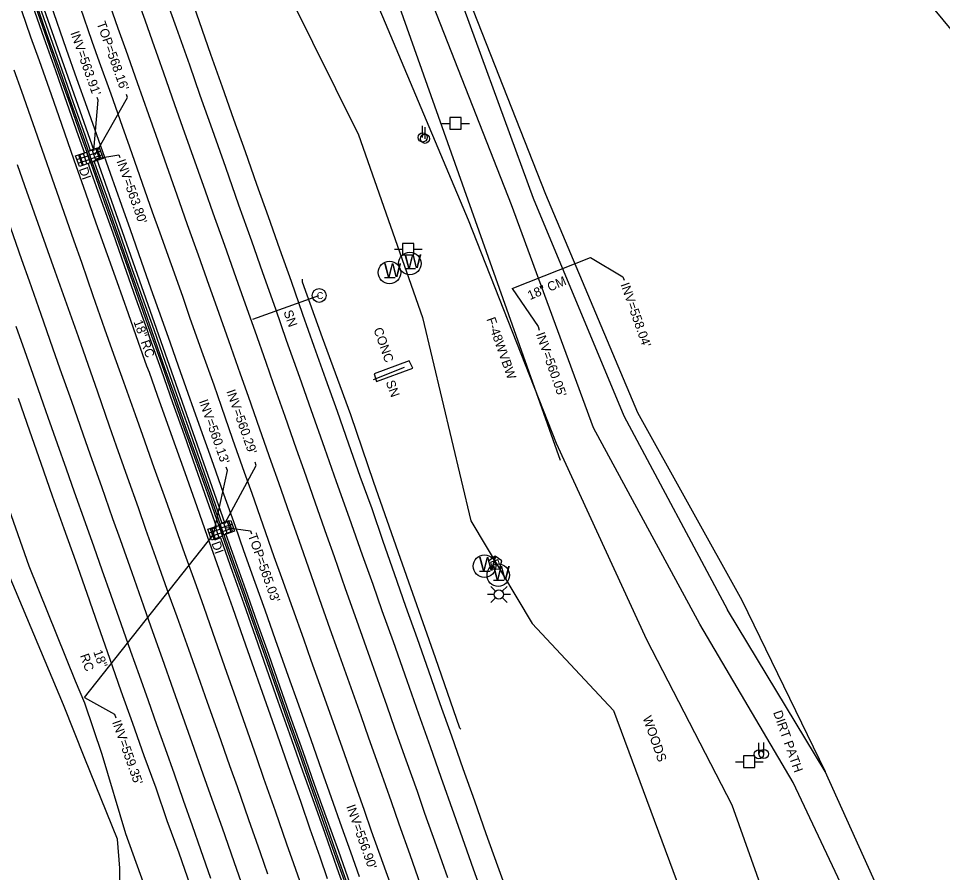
# Model space of a CAD drawing. Extents: x 2004847 to 2009016, y 1134161 to 1140101.
# Drawn here: x 2006254.5 to 2006657.2, y 1135789.7 to 1136161.7 of the extents above; entities that cross this region are included whole.
import ezdxf

# ---------------------------------------------------------------- set-up
doc = ezdxf.new("R2010")
doc.units = 0
for name, color, linetype in [('RD_EX_BldgApp', 7, 'Continuous'), ('RD_EX_Conc', 7, 'Continuous'), ('RD_EX_DR_Inlet', 7, 'Continuous'), ('RD_EX_DR_Inlet_txCode', 7, 'Continuous'), ('RD_EX_DR_Pipe', 7, 'Continuous'), ('RD_EX_DR_Pipe_txCode', 7, 'Continuous'), ('RD_EX_Driveway', 7, 'Continuous'), ('RD_EX_Fence_Other', 7, 'Continuous'), ('RD_EX_GuardRail', 7, 'Continuous'), ('RD_EX_H2O', 7, 'Continuous'), ('RD_EX_Pavement_Markings', 7, 'Continuous'), ('RD_EX_Road', 7, 'Continuous'), ('RD_EX_SU_Elec', 7, 'Continuous'), ('RD_EX_UT', 7, 'Continuous'), ('RD_EX_VEG', 7, 'Continuous'), ('RD_Sketch3', 7, 'Continuous')]:
    doc.layers.add(name, color=color, linetype=linetype)

msp = doc.modelspace()

# ---------------------------------------------------------------- linework, layer by layer
at = {"layer": 'RD_EX_BldgApp'}
for p, q in [((2006356.56, 1136030.74), (2006385.39, 1136041)), ((2006409.26, 1136004.5), (2006422.73, 1136009.77))]:
    msp.add_line(p, q, dxfattribs=at)
msp.add_circle((2006385.55, 1136041.06), 3, dxfattribs=at)
at = {"layer": 'RD_EX_Conc'}
for points in [[(2006261.87, 1136166.89), (2006266.82, 1136152.8), (2006271.82, 1136138.65), (2006276.81, 1136124.49), (2006281.81, 1136110.34), (2006286.83, 1136096.21), (2006291.85, 1136082.05), (2006296.79, 1136068), (2006301.8, 1136053.79), (2006306.81, 1136039.66), (2006311.8, 1136025.52), (2006316.78, 1136011.4), (2006321.74, 1135997.2), (2006326.74, 1135983.07), (2006331.82, 1135968.96), (2006336.81, 1135954.83), (2006341.84, 1135940.67), (2006346.82, 1135926.54), (2006351.83, 1135912.38), (2006356.79, 1135898.27), (2006361.81, 1135884.09), (2006366.78, 1135869.96), (2006371.77, 1135855.83), (2006376.79, 1135841.7), (2006381.8, 1135827.55), (2006386.76, 1135813.4), (2006392.11, 1135798.33), (2006397.11, 1135784.17)], [(2006262.53, 1136167.13), (2006267.48, 1136153.03), (2006272.5, 1136138.89), (2006277.48, 1136124.73), (2006282.5, 1136110.58), (2006287.49, 1136096.45), (2006292.51, 1136082.29), (2006297.49, 1136068.23), (2006302.5, 1136054.04), (2006307.51, 1136039.91), (2006312.48, 1136025.76), (2006317.45, 1136011.63), (2006322.43, 1135997.44), (2006327.43, 1135983.31), (2006332.53, 1135969.21), (2006337.53, 1135955.08), (2006342.52, 1135940.91), (2006347.52, 1135926.79), (2006352.54, 1135912.63), (2006357.48, 1135898.51), (2006362.52, 1135884.35), (2006367.5, 1135870.22), (2006372.49, 1135856.09), (2006377.5, 1135841.95), (2006382.51, 1135827.8), (2006387.53, 1135813.67), (2006392.86, 1135798.6), (2006397.85, 1135784.43)]]:
    msp.add_lwpolyline(points, dxfattribs=at)
msp.add_lwpolyline([(2006426.35, 1136009.4), (2006424.76, 1136012.54), (2006409.51, 1136006.93), (2006410.51, 1136003.52)], close=True, dxfattribs=at)
at = {"layer": 'RD_EX_DR_Inlet'}
for p, q in [((2006282.63, 1136102.99), (2006284.25, 1136098.26)), ((2006285.54, 1136102.24), (2006290.27, 1136103.86)), ((2006286.6, 1136104.4), (2006288.22, 1136099.67)), ((2006288.21, 1136104.95), (2006289.83, 1136100.22)), ((2006279.96, 1136100.28), (2006284.69, 1136101.9)), ((2006280.51, 1136098.67), (2006285.24, 1136100.29)), ((2006281.02, 1136102.44), (2006282.64, 1136097.71)), ((2006286.1, 1136100.63), (2006290.82, 1136102.25)), ((2006343.89, 1135942), (2006345.51, 1135937.27)), ((2006345.5, 1135942.55), (2006347.12, 1135937.82)), ((2006337.59, 1135937.64), (2006342.32, 1135939.27)), ((2006338.14, 1135936.04), (2006342.87, 1135937.66)), ((2006338.64, 1135939.8), (2006340.26, 1135935.07)), ((2006340.25, 1135940.36), (2006341.87, 1135935.63)), ((2006342.84, 1135939.84), (2006347.57, 1135941.46)), ((2006343.39, 1135938.23), (2006348.12, 1135939.86))]:
    msp.add_line(p, q, dxfattribs=at)
for points in [[(2006281.03, 1136097.16), (2006279.41, 1136101.89), (2006284.14, 1136103.51), (2006285.76, 1136098.78)], [(2006286.61, 1136099.11), (2006284.99, 1136103.84), (2006289.72, 1136105.47), (2006291.34, 1136100.74)], [(2006343.91, 1135936.72), (2006342.28, 1135941.45), (2006347.01, 1135943.07), (2006348.64, 1135938.34)], [(2006338.66, 1135934.52), (2006337.03, 1135939.25), (2006341.76, 1135940.87), (2006343.39, 1135936.15)]]:
    msp.add_lwpolyline(points, close=True, dxfattribs=at)
at = {"layer": 'RD_EX_DR_Inlet_txCode'}
for points in [[(2006287.37, 1136104.14), (2006289.17, 1136126.09), (2006288.74, 1136127.29)], [(2006287.96, 1136102.44), (2006302.01, 1136127.21), (2006301.52, 1136128.59)], [(2006288.55, 1136100.7), (2006298.24, 1136102.27), (2006298.64, 1136101.13)], [(2006503.74, 1136057.52), (2006517.92, 1136049.14), (2006518.42, 1136047.71)], [(2006469.59, 1136044.05), (2006480.94, 1136027.47), (2006481.47, 1136025.99)], [(2006339.54, 1135937), (2006345.59, 1135964.84), (2006345.08, 1135966.28)], [(2006344.44, 1135941.71), (2006358.12, 1135967.04), (2006357.63, 1135968.43)], [(2006345.05, 1135940.04), (2006355.59, 1135938.56), (2006356.04, 1135937.27)], [(2006283.21, 1135866.02), (2006296.3, 1135858.7), (2006296.89, 1135857.04)]]:
    msp.add_lwpolyline(points, dxfattribs=at)
at = {"layer": 'RD_EX_DR_Pipe'}
for p, q in [((2006230.99, 1136263.47), (2006287.37, 1136104.14)), ((2006288.55, 1136100.7), (2006344.44, 1135941.71)), ((2006469.59, 1136044.05), (2006503.74, 1136057.52)), ((2006283.21, 1135866.02), (2006339.54, 1135937))]:
    msp.add_line(p, q, dxfattribs=at)
at = {"layer": 'RD_EX_Driveway'}
for points in [[(2006320.55, 1136558.36), (2006344.22, 1136462.95), (2006367.47, 1136387.76), (2006397.5, 1136288.99), (2006440.84, 1136187.25), (2006478.74, 1136083.47), (2006518.32, 1135988.65), (2006563.43, 1135904.15)], [(2006551.41, 1135897.85), (2006505.13, 1135983.38), (2006469.38, 1136080.46), (2006429.34, 1136182.74), (2006387.99, 1136286.09), (2006354.86, 1136380.53), (2006334.03, 1136460.8), (2006306.37, 1136551.19)], [(2006666.77, 1135696.37), (2006647.18, 1135742.63), (2006606.03, 1135833.76), (2006563.43, 1135904.15)], [(2006656.28, 1135692.15), (2006634.83, 1135738.49), (2006592.17, 1135828.94), (2006551.41, 1135897.85)]]:
    msp.add_lwpolyline(points, dxfattribs=at)
at = {"layer": 'RD_EX_Fence_Other'}
msp.add_lwpolyline([(2006288.09, 1136544.58), (2006318.68, 1136456.24), (2006344.96, 1136379.7), (2006379.57, 1136282.04), (2006416.49, 1136178.27), (2006490.52, 1135969.29)], dxfattribs=at)
at = {"layer": 'RD_EX_GuardRail'}
msp.add_lwpolyline([(2006447.28, 1135852.21), (2006446.78, 1135852.58), (2006436.25, 1135883.27), (2006420.92, 1135926.56), (2006409.33, 1135959.56), (2006399.37, 1135989.06), (2006386.98, 1136022.61), (2006378.24, 1136046.92), (2006378.3, 1136048.22)], dxfattribs=at)
at = {"layer": 'RD_EX_H2O'}
for points in [[(2006438.3, 1136552.85), (2006448.54, 1136539.41), (2006461.27, 1136510.56), (2006479.77, 1136475.59), (2006499.97, 1136438.29), (2006517.79, 1136392.8), (2006547.32, 1136356.98), (2006571.18, 1136336.4), (2006576.82, 1136324.85), (2006567.33, 1136313.35), (2006581.05, 1136268.26), (2006602.92, 1136221.41), (2006633.34, 1136190.16), (2006666.45, 1136150.11), (2006686.25, 1136119.02), (2006695.17, 1136104.33)], [(2006169.58, 1136177.63), (2006207.33, 1136068.49), (2006240.4, 1135975.91), (2006259.05, 1135923.24), (2006279.18, 1135873.19), (2006283.21, 1135863.56), (2006290.81, 1135841.34), (2006301.16, 1135806.7), (2006317.11, 1135762.46), (2006327.77, 1135727.04)]]:
    msp.add_lwpolyline(points, dxfattribs=at)
at = {"layer": 'RD_EX_Pavement_Markings'}
for points in [[(2006304.5, 1136175.2), (2006309.51, 1136161.14), (2006312.8, 1136151.89), (2006317.67, 1136138.08), (2006322.55, 1136124.28), (2006326.05, 1136114.38), (2006335.84, 1136086.59), (2006339.22, 1136077.1), (2006344.24, 1136063.01), (2006349.26, 1136048.91), (2006352.62, 1136039.44), (2006357.45, 1136025.71), (2006362.28, 1136011.98), (2006365.56, 1136002.66), (2006370.55, 1135988.48), (2006375.54, 1135974.3), (2006378.82, 1135964.97), (2006383.8, 1135950.79), (2006388.78, 1135936.62), (2006392.07, 1135927.31), (2006396.94, 1135913.45), (2006401.81, 1135899.6), (2006405.11, 1135890.18), (2006410.07, 1135876.23), (2006415.04, 1135862.28), (2006418.42, 1135852.59), (2006423.3, 1135838.85), (2006428.18, 1135825.11), (2006431.52, 1135815.53), (2006436.48, 1135801.53), (2006441.44, 1135787.53)], [(2006292.95, 1136171.41), (2006297.85, 1136157.46), (2006301.32, 1136147.84), (2006306.23, 1136133.88), (2006311.14, 1136119.91), (2006314.29, 1136110.91), (2006324.51, 1136081.92), (2006328.06, 1136072.02), (2006332.77, 1136058.78), (2006337.48, 1136045.54), (2006340.96, 1136035.87), (2006346.03, 1136021.41), (2006351.11, 1136006.96), (2006354.61, 1135997.15), (2006359.52, 1135983), (2006364.43, 1135968.85), (2006367.79, 1135959.55), (2006372.66, 1135945.79), (2006377.53, 1135932.02), (2006380.87, 1135922.38), (2006385.57, 1135909.14), (2006390.26, 1135895.9), (2006393.56, 1135886.58), (2006398.61, 1135872.34), (2006403.66, 1135858.1), (2006407.04, 1135848.4), (2006411.96, 1135834.54), (2006416.89, 1135820.68), (2006420.32, 1135810.99), (2006425.05, 1135797.61), (2006429.77, 1135784.24)], [(2006457.26, 1135778.74), (2006452.86, 1135791.22), (2006449.06, 1135801.89), (2006444.41, 1135815.19), (2006438.76, 1135831.14), (2006434.02, 1135844.53), (2006429.04, 1135858.64), (2006423.83, 1135873.28), (2006417.88, 1135890.17), (2006413.07, 1135903.74), (2006409.03, 1135915.18), (2006404.42, 1135927.97), (2006398.77, 1135944.02), (2006393.15, 1135959.91), (2006388.07, 1135974.41), (2006382.09, 1135991.31), (2006377.14, 1136005.38), (2006371.36, 1136021.46), (2006366.61, 1136035.13), (2006361.03, 1136050.85), (2006356.19, 1136064.71), (2006350.6, 1136080.36), (2006344.85, 1136096.72), (2006339.03, 1136113.21), (2006333.72, 1136128.12), (2006329.11, 1136141.41), (2006323.36, 1136157.6), (2006317.84, 1136173.05)], [(2006268.38, 1136168.14), (2006275.31, 1136148.35), (2006279.82, 1136135.56), (2006284.23, 1136123.1), (2006289.34, 1136108.73), (2006294.45, 1136094.3), (2006299.46, 1136080.4), (2006303.13, 1136069.76), (2006308.01, 1136056.03), (2006312.24, 1136044.01), (2006316.82, 1136031.06), (2006320.59, 1136020.42), (2006324.08, 1136010.42), (2006327.45, 1136000.9), (2006331.69, 1135989.05), (2006335.86, 1135977.31), (2006339.29, 1135967.61), (2006343.83, 1135954.72), (2006348.87, 1135940.55), (2006352.61, 1135929.92), (2006357.45, 1135916.25), (2006361.79, 1135904.14), (2006366.37, 1135891.15), (2006372.79, 1135873.24), (2006375.78, 1135864.83), (2006381.87, 1135847.6), (2006386.58, 1135834.27), (2006390.82, 1135822.34), (2006395.34, 1135809.63), (2006399.18, 1135798.7), (2006402.97, 1135787.95)], [(2006255.84, 1136165.21), (2006259.8, 1136153.76), (2006263.5, 1136143.4), (2006268.72, 1136128.59), (2006273.19, 1136115.63), (2006278.64, 1136100.15), (2006283.65, 1136085.81), (2006288.26, 1136072.75), (2006293.21, 1136058.96), (2006297.31, 1136047.21), (2006302.25, 1136033.21), (2006306.69, 1136020.72), (2006310.36, 1136010.39), (2006311.39, 1136007.64), (2006314.99, 1135997.61), (2006320.94, 1135980.88), (2006326.93, 1135963.95), (2006332.21, 1135949.11), (2006336.72, 1135936.29), (2006342.74, 1135919.39), (2006347.78, 1135905.16), (2006352.46, 1135891.8), (2006356.26, 1135881.09), (2006360.7, 1135868.34), (2006365.07, 1135855.99), (2006369.41, 1135843.43), (2006372.94, 1135833.44), (2006377.49, 1135820.34), (2006381.49, 1135808.8), (2006385.83, 1135796.55), (2006389.06, 1135787.19)], [(2006281.31, 1136166.68), (2006286.53, 1136151.84), (2006289.7, 1136142.85), (2006294.7, 1136128.81), (2006299.7, 1136114.78), (2006302.84, 1136105.78), (2006312.77, 1136077.53), (2006316.03, 1136068.31), (2006321.01, 1136054.51), (2006325.98, 1136040.71), (2006329.08, 1136031.65), (2006334.33, 1136016.89), (2006339.59, 1136002.12), (2006342.82, 1135992.86), (2006347.84, 1135978.51), (2006352.87, 1135964.16), (2006356.14, 1135954.99), (2006360.98, 1135941.2), (2006365.83, 1135927.41), (2006369.1, 1135918.2), (2006373.89, 1135904.84), (2006378.69, 1135891.49), (2006381.86, 1135882.28), (2006387.11, 1135867.68), (2006392.37, 1135853.07), (2006395.53, 1135843.99), (2006400.34, 1135830.44), (2006405.14, 1135816.89), (2006408.22, 1135807.91), (2006413.27, 1135793.79), (2006418.33, 1135779.67)], [(2006252.54, 1136139.29), (2006255.81, 1136130.1), (2006265.75, 1136101.8), (2006269.06, 1136092.34), (2006278.6, 1136064.82), (2006278.6, 1136064.81), (2006281.89, 1136055.63), (2006286.95, 1136041.1), (2006292.01, 1136026.57), (2006295.15, 1136017.56), (2006300.24, 1136003.4), (2006305.32, 1135989.23), (2006308.52, 1135980.21), (2006313.55, 1135966.18), (2006318.58, 1135952.15), (2006321.9, 1135942.73), (2006326.92, 1135928.7), (2006331.94, 1135914.68), (2006335.34, 1135905.26), (2006340.26, 1135891.13), (2006345.19, 1135877), (2006348.37, 1135868.02), (2006353.28, 1135853.92), (2006358.19, 1135839.83), (2006361.28, 1135830.86), (2006366.3, 1135816.55), (2006371.33, 1135802.23), (2006374.42, 1135793.72), (2006379.49, 1135779.21)], [(2006253.89, 1136098.1), (2006257.1, 1136088.96), (2006267.09, 1136060.62), (2006270.32, 1136051.66), (2006275.39, 1136037.45), (2006280.46, 1136023.24), (2006283.69, 1136013.97), (2006288.88, 1135999.13), (2006294.06, 1135984.29), (2006297.13, 1135975.61), (2006301.88, 1135962.13), (2006306.63, 1135948.65), (2006309.9, 1135939.33), (2006314.99, 1135924.99), (2006320.08, 1135910.66), (2006323.44, 1135901.25), (2006328.53, 1135886.96), (2006333.62, 1135872.68), (2006336.74, 1135863.86), (2006341.62, 1135850.09), (2006346.51, 1135836.32), (2006349.81, 1135827.12), (2006354.8, 1135812.79), (2006359.78, 1135798.45), (2006362.98, 1135789.13)], [(2006245.9, 1136084.76), (2006255.88, 1136056.69), (2006259.17, 1136047.5), (2006264.26, 1136032.86), (2006269.34, 1136018.21), (2006272.57, 1136009.16), (2006277.54, 1135995.01), (2006282.52, 1135980.86), (2006285.78, 1135971.71), (2006290.66, 1135957.82), (2006295.54, 1135943.93), (2006298.87, 1135934.74), (2006303.95, 1135920.34), (2006309.02, 1135905.93), (2006312.25, 1135896.67), (2006317.08, 1135882.97), (2006321.91, 1135869.26), (2006325.28, 1135859.9), (2006330.07, 1135846.32), (2006334.87, 1135832.73), (2006338, 1135823.74), (2006343.21, 1135809.16), (2006348.42, 1135794.59), (2006351.62, 1135785.4)], [(2006253.34, 1136027.64), (2006257.17, 1136017.04), (2006260.77, 1136006.77), (2006265.25, 1135993.82), (2006267.32, 1135988.03), (2006271.36, 1135976.53), (2006275.22, 1135965.57), (2006278.76, 1135955.55), (2006283.54, 1135942.16), (2006287.31, 1135931.57), (2006290.85, 1135921.55), (2006294.71, 1135910.59), (2006299.09, 1135898.2), (2006303.3, 1135886.2), (2006307.05, 1135875.74), (2006310.97, 1135864.72), (2006314.7, 1135854.22), (2006318.39, 1135843.68), (2006322.29, 1135832.73), (2006326.33, 1135821.27), (2006330.17, 1135810.25), (2006333.84, 1135799.77), (2006338.19, 1135787.27)]]:
    msp.add_lwpolyline(points, dxfattribs=at)
at = {"layer": 'RD_EX_Road'}
msp.add_line((2006280.83, 1136102.22), (2006283.22, 1136103.07), dxfattribs=at)
for points in [[(2006227.36, 1136261.64), (2006230.66, 1136252.21), (2006235.69, 1136238.07), (2006240.66, 1136223.94), (2006245.65, 1136209.78), (2006250.61, 1136195.62), (2006255.61, 1136181.46), (2006260.63, 1136167.31), (2006265.59, 1136153.2), (2006270.58, 1136139.03), (2006275.54, 1136124.85), (2006280.51, 1136110.73), (2006283.22, 1136103.07)], [(2006229.89, 1136262.56), (2006233.47, 1136252.43), (2006238.49, 1136238.31), (2006243.5, 1136224.15), (2006248.45, 1136210.01), (2006253.42, 1136195.84), (2006258.41, 1136181.74), (2006263.44, 1136167.55), (2006268.39, 1136153.44), (2006273.39, 1136139.29), (2006278.37, 1136125.14), (2006283.39, 1136111), (2006285.76, 1136104.24)], [(2006327.95, 1136175.43), (2006333.21, 1136160.31), (2006338.13, 1136146.14), (2006343.2, 1136131.94), (2006348.23, 1136117.9), (2006353.26, 1136103.74), (2006358.29, 1136089.6), (2006363.28, 1136075.51), (2006368.31, 1136061.31), (2006373.29, 1136047.22), (2006378.25, 1136032.98), (2006383.2, 1136018.95), (2006388.36, 1136004.79), (2006393.38, 1135990.68), (2006398.3, 1135976.47), (2006403.28, 1135962.36), (2006408.43, 1135948.27), (2006413.28, 1135934.07), (2006418.19, 1135919.98), (2006423.17, 1135905.78), (2006428.21, 1135891.63), (2006433.24, 1135877.5), (2006438.17, 1135863.38), (2006443.16, 1135849.2), (2006448.13, 1135835.07), (2006453.17, 1135820.95), (2006458.23, 1135806.78), (2006463.24, 1135792.68), (2006468.28, 1135778.65)], [(2006287.36, 1136099.73), (2006290.39, 1136100.72), (2006288.76, 1136105.26), (2006285.76, 1136104.24)], [(2006284.83, 1136098.54), (2006282.42, 1136097.71), (2006280.83, 1136102.22)], [(2006287.36, 1136099.73), (2006288.38, 1136096.86), (2006293.43, 1136082.71), (2006298.38, 1136068.62), (2006303.37, 1136054.44), (2006308.38, 1136040.31), (2006313.44, 1136026.18), (2006318.38, 1136012.04), (2006323.41, 1135997.88), (2006328.4, 1135983.75), (2006333.37, 1135969.6), (2006338.37, 1135955.47), (2006343.15, 1135941.91)], [(2006284.83, 1136098.54), (2006285.51, 1136096.58), (2006290.56, 1136082.47), (2006295.55, 1136068.36), (2006300.56, 1136054.17), (2006305.52, 1136040.04), (2006310.53, 1136025.92), (2006311.66, 1136022.75), (2006316.62, 1136008.62), (2006321.56, 1135994.44), (2006326.65, 1135980.32), (2006331.62, 1135966.17), (2006336.56, 1135952.03), (2006340.87, 1135940.09)], [(2006254.34, 1135996.31), (2006259.32, 1135982.11), (2006264.29, 1135967.95), (2006269.23, 1135953.79), (2006274.29, 1135939.63), (2006279.29, 1135925.53), (2006284.28, 1135911.39), (2006289.19, 1135897.21), (2006294.13, 1135883.08), (2006299.17, 1135868.91), (2006304.18, 1135854.78), (2006309.14, 1135840.67), (2006314.43, 1135826.61), (2006319.18, 1135812.42), (2006324.36, 1135798.33), (2006329.27, 1135784.11)], [(2006344.78, 1135937.35), (2006347.8, 1135938.33), (2006346.2, 1135942.86), (2006343.15, 1135941.91)], [(2006342.5, 1135935.43), (2006339.93, 1135934.45), (2006338.21, 1135939.21), (2006340.87, 1135940.09)], [(2006342.5, 1135935.43), (2006342.62, 1135935.08), (2006347.62, 1135920.94), (2006352.64, 1135906.78), (2006357.59, 1135892.65), (2006362.64, 1135878.5), (2006367.6, 1135864.37), (2006372.63, 1135850.2), (2006377.56, 1135836.08), (2006382.68, 1135821.94), (2006387.99, 1135806.9), (2006393.28, 1135791.77), (2006398.31, 1135777.7), (2006403.3, 1135763.51), (2006403.59, 1135762.69)], [(2006344.78, 1135937.35), (2006348.35, 1135927.18), (2006353.37, 1135913.03), (2006358.38, 1135898.92), (2006363.42, 1135884.76), (2006368.4, 1135870.63), (2006373.39, 1135856.5), (2006378.43, 1135842.38), (2006383.43, 1135828.23), (2006388.51, 1135814.12), (2006393.91, 1135799.08), (2006398.91, 1135784.92), (2006403.76, 1135770.76), (2006405.94, 1135764.55)]]:
    msp.add_lwpolyline(points, dxfattribs=at)
at = {"layer": 'RD_EX_SU_Elec'}
msp.add_lwpolyline([(2006465.2, 1135925.43), (2006462.24, 1135927.46), (2006459.4, 1135925.28), (2006460.59, 1135921.9), (2006464.17, 1135921.99)], close=True, dxfattribs=at)
at = {"layer": 'RD_EX_UT'}
for p, q in [((2006430.63, 1136109.89), (2006430.63, 1136114.89)), ((2006439, 1136115.98), (2006442.47, 1136115.98)), ((2006447.44, 1136118.55), (2006442.44, 1136118.55)), ((2006442.44, 1136118.55), (2006442.44, 1136113.55)), ((2006447.36, 1136115.98), (2006451, 1136115.98)), ((2006447.44, 1136113.55), (2006447.44, 1136118.55)), ((2006431.69, 1136109.31), (2006431.69, 1136114.31)), ((2006442.44, 1136113.55), (2006447.44, 1136113.55)), ((2006426.79, 1136063.73), (2006421.79, 1136063.73)), ((2006421.79, 1136063.73), (2006421.79, 1136058.73)), ((2006426.79, 1136058.73), (2006426.79, 1136063.73)), ((2006418.36, 1136061.16), (2006421.83, 1136061.16)), ((2006421.79, 1136058.73), (2006426.79, 1136058.73)), ((2006426.72, 1136061.16), (2006430.36, 1136061.16)), ((2006422.92, 1136052.75), (2006427.55, 1136052.75)), ((2006414.08, 1136048.89), (2006418.71, 1136048.89)), ((2006455.48, 1135920.97), (2006460.11, 1135920.97)), ((2006460.37, 1135914.37), (2006462.46, 1135912.28)), ((2006461.47, 1135917.05), (2006466.1, 1135917.05)), ((2006465.28, 1135912.21), (2006467.44, 1135914.37)), ((2006461.84, 1135910.84), (2006458.9, 1135910.84)), ((2006465.29, 1135909.45), (2006467.44, 1135907.3)), ((2006468.9, 1135910.84), (2006465.84, 1135910.84)), ((2006460.37, 1135907.3), (2006462.45, 1135909.38)), ((2006577.16, 1135841.18), (2006577.16, 1135846.18)), ((2006579.36, 1135841.37), (2006579.36, 1135846.37)), ((2006567.02, 1135837.93), (2006570.49, 1135837.93)), ((2006575.45, 1135840.49), (2006570.45, 1135840.49)), ((2006570.45, 1135840.49), (2006570.45, 1135835.49)), ((2006575.38, 1135837.93), (2006579.02, 1135837.93)), ((2006575.45, 1135835.49), (2006575.45, 1135840.49)), ((2006570.45, 1135835.49), (2006575.45, 1135835.49))]:
    msp.add_line(p, q, dxfattribs=at)
for centre, radius in [((2006430.63, 1136109.89), 2), ((2006431.69, 1136109.31), 2), ((2006425.05, 1136054.96), 4.91), ((2006416.21, 1136051.1), 4.91), ((2006457.61, 1135923.18), 4.91), ((2006463.6, 1135919.25), 4.91), ((2006463.84, 1135910.82), 2), ((2006577.16, 1135841.18), 2), ((2006579.36, 1135841.37), 2)]:
    msp.add_circle(centre, radius, dxfattribs=at)
at = {"layer": 'RD_EX_VEG'}
for points in [[(2006322.66, 1136558.8), (2006353.02, 1136466.99), (2006384.47, 1136394.39), (2006412, 1136295.24), (2006443.56, 1136188.55), (2006484.2, 1136085.12), (2006524.25, 1135990.06), (2006569.76, 1135908.33), (2006606.1, 1135833.79)], [(2006565.48, 1135819.09), (2006528.32, 1135891.1), (2006489.01, 1135976.52), (2006450.61, 1136073.8), (2006408.25, 1136174.58), (2006367.76, 1136276.74), (2006335.67, 1136376.41), (2006311.68, 1136456.94), (2006280.68, 1136541.58)], [(2006329.42, 1136220.78), (2006352.55, 1136212.1), (2006402.65, 1136111.04), (2006430.53, 1136031.48), (2006451.57, 1135942.9), (2006478.35, 1135898.12), (2006513.78, 1135860.32), (2006547.83, 1135768.67), (2006577.61, 1135717.06), (2006602.57, 1135668.11), (2006642.32, 1135585.7)], [(2006322.5, 1135727.67), (2006311.4, 1135759.47), (2006298.58, 1135765.44), (2006298.64, 1135791.57), (2006297.71, 1135804.25), (2006283.46, 1135839.35), (2006274.08, 1135862.69), (2006250.13, 1135919.86), (2006228.17, 1135978.51), (2006200.66, 1136064.46), (2006167.02, 1136165.56)], [(2006642.32, 1135585.7), (2006661.69, 1135564.83), (2006650.25, 1135601.73), (2006631.52, 1135651.66), (2006598.58, 1135726.37), (2006565.48, 1135819.09)]]:
    msp.add_lwpolyline(points, dxfattribs=at)

# ---------------------------------------------------------------- texts
at = {"layer": 'RD_EX_BldgApp'}
msp.add_text('C', height=3, dxfattribs=at).set_placement((2006384.47, 1136039.5))
at = {"layer": 'RD_EX_DR_Inlet_txCode'}
for s, p in [("TOP=568.16'", (2006288.52, 1136159.63)), ("INV=563.91'", (2006277.06, 1136155.41)), ("INV=563.80'", (2006297.18, 1136099.6)), ('DI', (2006280.74, 1136096.1)), ("INV=558.04'", (2006516.79, 1136045.84)), ("INV=560.05'", (2006479.95, 1136024.23)), ("INV=560.29'", (2006345.03, 1135999.31)), ("INV=560.13'", (2006333.11, 1135994.99)), ("TOP=565.03'", (2006354.43, 1135936.62)), ('DI', (2006338.54, 1135933.13)), ("INV=559.35'", (2006295.29, 1135855.26)), ("INV=556.90'", (2006397.29, 1135818.51))]:
    msp.add_text(s, height=4, rotation=289.4494, dxfattribs=at).set_placement(p)
at = {"layer": 'RD_EX_DR_Pipe_txCode'}
for s, rotation, p in [('18" CM', 23.0189, (2006477.39, 1136039)), ('18" RC', 289.4494, (2006304.57, 1136029.63)), ('18"', 289.4494, (2006287.03, 1135885.91)), ('RC', 289.4494, (2006281.26, 1135884.24))]:
    msp.add_text(s, height=4, rotation=rotation, dxfattribs=at).set_placement(p)
at = {"layer": 'RD_EX_SU_Elec'}
msp.add_text('E', height=3.75, rotation=289.4494, dxfattribs=at).set_placement((2006459.86, 1135925.4))
at = {"layer": 'RD_EX_UT'}
for p in [(2006422.59, 1136052.96), (2006413.75, 1136049.1), (2006455.14, 1135921.18), (2006461.14, 1135917.25)]:
    msp.add_text('W', height=6, dxfattribs=at).set_placement(p)
at = {"layer": 'RD_Sketch3'}
for s, p in [('SN', (2006369.95, 1136033.9)), ('F-48WVBW', (2006458.39, 1136030.77)), ('CONC', (2006409.15, 1136026.31)), ('SN', (2006414.52, 1136003.34)), ('WOODS', (2006526.47, 1135857.13)), ('DIRT PATH', (2006583.33, 1135859.5))]:
    msp.add_text(s, height=4, rotation=289.4494, dxfattribs=at).set_placement(p)

doc.saveas('drawing.dxf')
